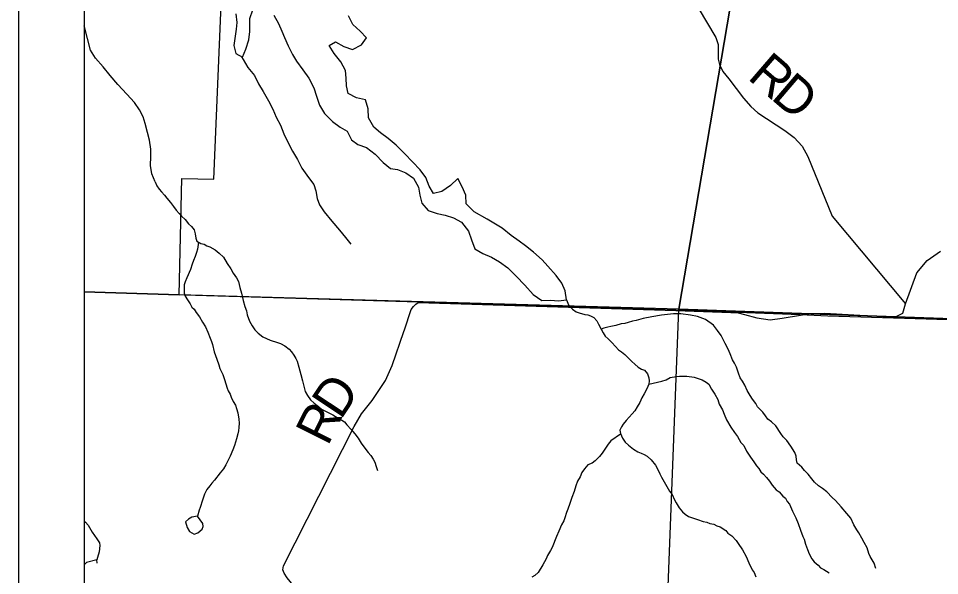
# Model space of a CAD drawing. Extents: x 0 to 34, y 0 to 22.
# Drawn here: x 2 to 3.401, y 19.379 to 20.228 of the extents above; entities that cross this region are included whole.
import ezdxf

# ---------------------------------------------------------------- set-up
doc = ezdxf.new("R2010")
doc.units = 0
for name, color, linetype in [('Default', 7, 'Continuous'), ('GM_X_County_Road', 7, 'Continuous'), ('GM_X_County_Road_Text', 7, 'Continuous'), ('GM_X_Major_Lake', 7, 'Continuous'), ('GM_X_Minor_River', 7, 'Continuous'), ('GM_X_Section', 7, 'Continuous'), ('GM_X_State_Route', 7, 'Continuous'), ('SH_Data', 7, 'Continuous')]:
    doc.layers.add(name, color=color, linetype=linetype)

msp = doc.modelspace()

# ---------------------------------------------------------------- linework, layer by layer
at = {"layer": 'Default'}
for points in [[(2.1, 20.7541), (2.1, 19.8111), (2.2447, 19.8069), (2.2486, 19.9841), (2.2971, 19.9829), (2.3292, 20.7433)], [(2.1, 19.8111), (2.1, 18.8179), (2.9671, 18.8096), (3.0048, 19.785), (2.2447, 19.8069)]]:
    msp.add_lwpolyline(points, close=True, dxfattribs=at)
at = {"layer": 'GM_X_County_Road'}
for points in [[(3.0342, 20.2435), (3.0612, 20.1987), (3.0648, 20.1877), (3.0644, 20.1657), (3.0666, 20.1575), (3.0719, 20.1469), (3.0808, 20.1355), (3.1031, 20.1064), (3.1141, 20.0933), (3.1251, 20.0837), (3.166, 20.057), (3.1802, 20.0464), (3.1923, 20.0333), (3.2008, 20.0173), (3.2382, 19.9266), (3.3496, 19.7928), (3.3669, 19.8402), (3.3827, 19.8589), (3.403, 19.8734)], [(2.5863, 19.7508), (2.5873, 19.7536), (2.5977, 19.7842), (2.6012, 19.7891), (2.6046, 19.7927), (2.6082, 19.795), (3.0004, 19.7831), (3.0837, 19.7798), (3.0891, 19.7798), (3.0949, 19.7794), (3.1045, 19.7767), (3.1233, 19.7717), (3.1436, 19.7685), (3.1618, 19.771), (3.1898, 19.7756), (3.2063, 19.7785), (3.2271, 19.779), (3.3334, 19.7729), (3.3456, 19.779), (3.3496, 19.7928)], [(2.4536, 18.3939), (2.4734, 18.9711), (2.4789, 19.2126), (2.4779, 19.2343), (2.4729, 19.258), (2.466, 19.2847), (2.4564, 19.3082), (2.4379, 19.3402), (2.4089, 19.3759), (2.4042, 19.3829), (2.4024, 19.3879), (2.4033, 19.3939), (2.5108, 19.6061), (2.522, 19.6255), (2.5381, 19.646), (2.5504, 19.6643), (2.5583, 19.6763), (2.5688, 19.6992), (2.5863, 19.7508)]]:
    msp.add_lwpolyline(points, dxfattribs=at)
at = {"layer": 'GM_X_Major_Lake'}
for points in [[(2.3308, 20.2347), (2.3324, 20.2213), (2.3311, 20.2115), (2.3275, 20.1864), (2.3306, 20.1742), (2.3407, 20.1687), (2.3459, 20.1807), (2.3504, 20.1951), (2.3522, 20.2079), (2.3521, 20.2174), (2.3523, 20.2273), (2.3564, 20.2405)], [(2.3885, 20.2326), (2.3958, 20.2199), (2.4009, 20.2084), (2.4048, 20.1988), (2.4102, 20.1857), (2.4171, 20.1726), (2.423, 20.1626), (2.4329, 20.1495), (2.4418, 20.1367), (2.4494, 20.1217), (2.4537, 20.1094), (2.4579, 20.0957), (2.4656, 20.0826), (2.4779, 20.0705), (2.4894, 20.0622), (2.5003, 20.0559), (2.5065, 20.0428), (2.5162, 20.0354), (2.5294, 20.0309), (2.5428, 20.0211), (2.5551, 20.0083), (2.5662, 19.9989), (2.5768, 19.9975), (2.5893, 19.9927), (2.6012, 19.9844), (2.6089, 19.9709), (2.6105, 19.9587), (2.6136, 19.9461), (2.6236, 19.9353), (2.6372, 19.9304), (2.6493, 19.9282), (2.6617, 19.9241), (2.6741, 19.9174), (2.6848, 19.9038), (2.6891, 19.8904), (2.6945, 19.877), (2.7068, 19.8695), (2.72, 19.8639), (2.732, 19.8568), (2.7447, 19.8477), (2.7573, 19.8353), (2.7707, 19.8213), (2.7833, 19.8073), (2.7964, 19.7983), (2.8093, 19.7984), (2.8218, 19.7977), (2.834, 19.7989), (2.832, 19.8127), (2.8266, 19.8246), (2.8181, 19.8362), (2.8055, 19.8502), (2.7966, 19.8599), (2.7836, 19.8719), (2.7717, 19.8813), (2.7616, 19.8884), (2.7496, 19.897), (2.7358, 19.908), (2.7231, 19.9159), (2.713, 19.9222), (2.6935, 19.9333), (2.6812, 19.9454), (2.6808, 19.9587), (2.675, 19.9714), (2.6684, 19.9841), (2.6575, 19.9733), (2.6444, 19.9641), (2.6314, 19.9609), (2.6249, 19.9721)], [(2.6249, 19.9721), (2.6198, 19.9852), (2.611, 19.9971), (2.588, 20.0212), (2.5746, 20.0345), (2.5627, 20.0446), (2.5508, 20.0536), (2.5407, 20.0618), (2.5327, 20.0761), (2.5322, 20.0902), (2.528, 20.1036), (2.5144, 20.1069), (2.5016, 20.1133), (2.4992, 20.1248), (2.4987, 20.1366), (2.4975, 20.1484), (2.4906, 20.1615), (2.4806, 20.1742), (2.4729, 20.1866), (2.4825, 20.1921), (2.4953, 20.1849), (2.5084, 20.1801), (2.5219, 20.1874), (2.5297, 20.1982), (2.5197, 20.2083), (2.5089, 20.2185), (2.5024, 20.2315)], [(2.1, 20.208), (2.102, 20.2086), (2.1, 20.2162)]]:
    msp.add_lwpolyline(points, dxfattribs=at)
at = {"layer": 'GM_X_Minor_River'}
for p, q in [((2.2808, 19.4587), (2.2722, 19.4695)), ((2.1199, 19.398), (2.1193, 19.4031))]:
    msp.add_line(p, q, dxfattribs=at)
for points in [[(2.2079, 19.9787), (2.203, 19.9911), (2.2007, 20.0037), (2.2017, 20.0174), (2.2016, 20.0284), (2.1996, 20.0422), (2.1965, 20.0537), (2.193, 20.0678), (2.1898, 20.0778), (2.184, 20.0885), (2.1766, 20.0997), (2.1648, 20.1125), (2.1514, 20.1269), (2.1396, 20.1405), (2.1289, 20.1537), (2.1174, 20.1669), (2.1097, 20.1792), (2.1003, 20.215)], [(2.3396, 20.1693), (2.342, 20.165), (2.3489, 20.153), (2.3592, 20.1409), (2.3653, 20.1282), (2.3726, 20.1162), (2.3806, 20.1023), (2.3871, 20.0896), (2.3921, 20.0773), (2.3986, 20.065), (2.4039, 20.0519), (2.4097, 20.0392), (2.4169, 20.0253), (2.4246, 20.0126), (2.4311, 19.9994), (2.4413, 19.9855)], [(2.4413, 19.9855), (2.4492, 19.9745), (2.4523, 19.9649), (2.4546, 19.9534), (2.4582, 19.9438), (2.4654, 19.9329), (2.4768, 19.9189), (2.4886, 19.9053), (2.4977, 19.894), (2.5058, 19.8839)], [(2.2079, 19.9787), (2.2104, 19.9729), (2.214, 19.9678), (2.2176, 19.9635), (2.2224, 19.9584), (2.226, 19.9537), (2.2315, 19.9471), (2.2358, 19.9412), (2.2402, 19.9357), (2.2446, 19.9306), (2.2482, 19.9263), (2.2537, 19.9212), (2.2588, 19.9149), (2.2632, 19.9106), (2.2676, 19.9055), (2.269, 19.8998), (2.2699, 19.8929), (2.2712, 19.8883), (2.2776, 19.885), (2.2828, 19.8837), (2.2869, 19.8813), (2.2914, 19.8796), (2.2992, 19.8752), (2.3055, 19.8704), (2.3118, 19.8641), (2.3175, 19.8544), (2.3233, 19.8462), (2.3269, 19.8396), (2.3319, 19.8326), (2.3348, 19.8268), (2.3371, 19.818), (2.3395, 19.8095), (2.3421, 19.798), (2.3445, 19.7888), (2.3469, 19.7823), (2.3482, 19.7765), (2.3517, 19.7665), (2.3556, 19.7596), (2.3599, 19.7533), (2.3647, 19.7486), (2.3721, 19.743), (2.3829, 19.7377), (2.3942, 19.7343), (2.3987, 19.7326), (2.4054, 19.7293), (2.4117, 19.7242), (2.4154, 19.7199), (2.419, 19.7148), (2.4222, 19.7098), (2.4243, 19.7055), (2.4267, 19.6967), (2.4297, 19.6856), (2.4321, 19.676), (2.4337, 19.6695), (2.4364, 19.6595), (2.4396, 19.6533), (2.4443, 19.647), (2.4499, 19.6419), (2.4565, 19.6367), (2.4613, 19.6328), (2.4703, 19.6279), (2.4781, 19.6238), (2.4863, 19.619), (2.4922, 19.6157), (2.4963, 19.6133), (2.4996, 19.6086), (2.5062, 19.6016), (2.512, 19.5949), (2.5171, 19.5883), (2.5214, 19.5809), (2.5272, 19.5731), (2.5323, 19.5668), (2.5363, 19.5621), (2.5399, 19.5563), (2.542, 19.5517), (2.5445, 19.5451), (2.5465, 19.539)], [(2.2738, 19.887), (2.2727, 19.8765), (2.271, 19.8712), (2.2689, 19.8652), (2.2664, 19.8592), (2.2643, 19.8532), (2.2618, 19.8453), (2.256, 19.8326), (2.2539, 19.8266), (2.2522, 19.8221), (2.252, 19.8171), (2.2522, 19.8095), (2.2539, 19.8045), (2.2571, 19.7991), (2.2611, 19.7929), (2.2636, 19.7878), (2.2676, 19.785), (2.2705, 19.78), (2.2756, 19.773), (2.2802, 19.7652), (2.2845, 19.7579), (2.2881, 19.7501), (2.2915, 19.7409), (2.2936, 19.7355), (2.2954, 19.7309), (2.298, 19.7201), (2.3018, 19.7086), (2.3049, 19.7001), (2.3066, 19.6944), (2.3109, 19.6855), (2.3133, 19.6778), (2.3174, 19.6647), (2.3191, 19.6605), (2.3224, 19.6554), (2.3237, 19.6508), (2.3269, 19.6443), (2.3302, 19.6385), (2.3319, 19.6338), (2.3336, 19.6273), (2.3351, 19.6174), (2.3357, 19.6113), (2.3354, 19.6045), (2.3349, 19.5999), (2.334, 19.595), (2.3318, 19.5875), (2.3288, 19.5773), (2.3263, 19.5706), (2.3222, 19.5612), (2.3189, 19.5552), (2.3156, 19.5481), (2.312, 19.5418), (2.3068, 19.5355), (2.2981, 19.5244), (2.2942, 19.52), (2.291, 19.5159), (2.2866, 19.5104), (2.2833, 19.5033), (2.2817, 19.4988), (2.28, 19.4943), (2.2766, 19.483), (2.2749, 19.4789), (2.2722, 19.4695)], [(2.834, 19.7989), (2.837, 19.7915), (2.8428, 19.7849), (2.8484, 19.7809), (2.8533, 19.7792), (2.8615, 19.777), (2.8664, 19.7761), (2.8706, 19.7748), (2.8754, 19.772), (2.8802, 19.7672), (2.8827, 19.7622), (2.8866, 19.7545), (2.8898, 19.7487), (2.8927, 19.744), (2.8971, 19.7397), (2.9026, 19.7342), (2.9084, 19.7279), (2.9132, 19.7232), (2.9173, 19.72), (2.9228, 19.716), (2.9272, 19.7113), (2.9335, 19.705), (2.9379, 19.7014), (2.943, 19.6967), (2.9479, 19.6934), (2.9524, 19.6922), (2.9571, 19.6867), (2.9592, 19.6805), (2.9598, 19.6759), (2.9592, 19.6706), (2.9563, 19.6635), (2.9519, 19.6561), (2.9486, 19.6501), (2.9453, 19.6426), (2.9413, 19.6363), (2.9377, 19.6299), (2.9337, 19.6255), (2.929, 19.6204), (2.9247, 19.6156), (2.9203, 19.6097), (2.9175, 19.6056), (2.915, 19.6007), (2.916, 19.5954), (2.9192, 19.5884), (2.9231, 19.5826), (2.9283, 19.5778), (2.9357, 19.5715), (2.9424, 19.5678), (2.9476, 19.5658), (2.9521, 19.5637), (2.9566, 19.5613), (2.9628, 19.5554), (2.9694, 19.5475), (2.9726, 19.541), (2.9761, 19.534), (2.9786, 19.5293), (2.9843, 19.5185), (2.9908, 19.508), (2.9948, 19.5029), (2.9983, 19.4945), (3.0008, 19.4898), (3.0051, 19.4824), (3.0102, 19.4762), (3.0146, 19.4726), (3.0195, 19.4694), (3.033, 19.4644), (3.0416, 19.4618), (3.0472, 19.4605), (3.0517, 19.4584), (3.0582, 19.4574), (3.0626, 19.455), (3.0679, 19.4533), (3.0761, 19.4481), (3.0793, 19.4438), (3.0856, 19.4397), (3.0922, 19.4327), (3.0951, 19.428), (3.1016, 19.4183), (3.1073, 19.4082), (3.1115, 19.3986), (3.1161, 19.3881), (3.1194, 19.3838), (3.1218, 19.3773)], [(3.3045, 19.39), (3.3017, 19.3981), (3.296, 19.4081), (3.2939, 19.4131), (3.2912, 19.4216), (3.2865, 19.4294), (3.2833, 19.4363), (3.2787, 19.4441), (3.2758, 19.4491), (3.2711, 19.4565), (3.2662, 19.4669), (3.2603, 19.474), (3.2519, 19.4841), (3.2432, 19.4936), (3.238, 19.4979), (3.23, 19.507), (3.2233, 19.5117), (3.2173, 19.5157), (3.2111, 19.5213), (3.2071, 19.5264), (3.2016, 19.5338), (3.1958, 19.5393), (3.1921, 19.5444), (3.1848, 19.5503), (3.1838, 19.5553), (3.1832, 19.561), (3.1811, 19.5668), (3.175, 19.5761), (3.1689, 19.5847), (3.1637, 19.5906), (3.1601, 19.5956), (3.1522, 19.6073), (3.1459, 19.6132), (3.14, 19.6176), (3.1364, 19.6227), (3.1324, 19.6281), (3.1247, 19.636), (3.1218, 19.6414), (3.1168, 19.6481), (3.1135, 19.6535), (3.1085, 19.6613), (3.105, 19.669), (3.1018, 19.6752), (3.0981, 19.6803), (3.0953, 19.6876), (3.0926, 19.6964), (3.0894, 19.7026), (3.0866, 19.708), (3.0831, 19.7169), (3.0799, 19.7238), (3.0753, 19.7327), (3.0724, 19.7385), (3.0692, 19.7447), (3.0634, 19.7525), (3.0573, 19.7607), (3.0454, 19.7691), (3.0334, 19.7737), (3.0225, 19.776), (3.0077, 19.7776), (2.9967, 19.778), (2.9784, 19.7756), (2.9635, 19.7731), (2.9505, 19.7709), (2.9398, 19.7675), (2.9344, 19.7665), (2.9279, 19.7644), (2.9226, 19.7631), (2.9168, 19.7625), (2.9088, 19.7602), (2.9015, 19.7585), (2.8965, 19.7576), (2.8908, 19.7562), (2.8865, 19.7546)], [(2.9593, 19.6709), (2.9791, 19.6753), (2.9856, 19.6773), (2.9915, 19.6809), (3.0014, 19.6825), (3.006, 19.6827), (3.017, 19.6827), (3.0279, 19.6812), (3.0358, 19.679), (3.0403, 19.6773), (3.0463, 19.6737), (3.0503, 19.6705), (3.0546, 19.6631), (3.0593, 19.6554), (3.064, 19.6476), (3.066, 19.6403), (3.071, 19.6314), (3.0738, 19.6249), (3.0773, 19.6164), (3.0838, 19.6051), (3.0896, 19.5973), (3.0939, 19.5911), (3.0993, 19.5818), (3.1037, 19.5775), (3.1079, 19.5686), (3.1137, 19.5596), (3.1188, 19.5522), (3.1231, 19.5464), (3.1264, 19.5421), (3.1296, 19.5374), (3.1337, 19.5335), (3.1381, 19.5284), (3.1428, 19.5229), (3.1468, 19.5171), (3.153, 19.51), (3.1574, 19.5068), (3.1629, 19.5002), (3.167, 19.497), (3.1695, 19.4923), (3.1731, 19.488), (3.1777, 19.4772), (3.183, 19.4672), (3.1865, 19.4587), (3.19, 19.4483), (3.1934, 19.439), (3.1956, 19.4348), (3.1976, 19.4271), (3.2007, 19.419), (3.2031, 19.4125), (3.2071, 19.4048), (3.2107, 19.4004), (3.2166, 19.3953), (3.2202, 19.391), (3.2255, 19.3885), (3.2333, 19.3833)], [(2.9162, 19.5948), (2.9012, 19.5845), (2.8972, 19.5793), (2.892, 19.5715), (2.888, 19.5659), (2.884, 19.5607), (2.8777, 19.5541), (2.8727, 19.5505), (2.8665, 19.5477), (2.861, 19.5418), (2.8574, 19.5362), (2.8545, 19.5298), (2.8505, 19.5228), (2.8479, 19.516), (2.8454, 19.5074), (2.842, 19.4983), (2.839, 19.4889), (2.8361, 19.4803), (2.834, 19.4751), (2.8315, 19.4672), (2.8298, 19.4627), (2.8265, 19.4563), (2.8224, 19.447), (2.8187, 19.4387), (2.8121, 19.4222), (2.8096, 19.4174), (2.8052, 19.4099), (2.8027, 19.4047), (2.7978, 19.3954), (2.7906, 19.3838), (2.7859, 19.3794), (2.7809, 19.3766)], [(2.2722, 19.4695), (2.2639, 19.4683), (2.2589, 19.4654), (2.2542, 19.461), (2.2566, 19.4525), (2.2603, 19.4464), (2.2674, 19.4424), (2.2732, 19.4445), (2.2794, 19.4497), (2.281, 19.4538), (2.2808, 19.4587)], [(2.1, 19.4621), (2.1019, 19.4605), (2.1059, 19.4562), (2.1124, 19.4453), (2.1192, 19.4352), (2.1236, 19.429), (2.1238, 19.4248), (2.1227, 19.4153), (2.1205, 19.4067), (2.1193, 19.4031)], [(2.1193, 19.4031), (2.1036, 19.3992), (2.1, 19.3958)]]:
    msp.add_lwpolyline(points, dxfattribs=at)
at = {"layer": 'GM_X_Section'}
for points in [[(2.3292, 20.7433), (3.1645, 20.7261), (3.0048, 19.785), (2.2447, 19.8069), (2.2486, 19.9841), (2.2971, 19.9829)], [(3.1645, 20.7261), (4.3261, 20.699), (4.3194, 20.2817), (4.3193, 20.2753), (4.3164, 20.0605), (4.2362, 19.9572), (4.2253, 19.9438), (4.2171, 19.9357), (4.2598, 19.9346), (4.2313, 19.8855), (4.2007, 19.856), (4.1813, 19.8371), (4.1568, 19.8116), (4.1378, 19.745), (3.0048, 19.785)]]:
    msp.add_lwpolyline(points, close=True, dxfattribs=at)
msp.add_lwpolyline([(3.9584, 18.8022), (2.9671, 18.8096), (3.0048, 19.785), (4.1378, 19.745)], dxfattribs=at)
at = {"layer": 'GM_X_State_Route'}
msp.add_lwpolyline([(3.4964, 19.7659), (3.3482, 19.7707), (3.2315, 19.7745), (3.1896, 19.7761), (3.0947, 19.7799), (3.0889, 19.7803), (3.0835, 19.7803), (3.0002, 19.7836), (2.608, 19.7955), (2.1, 19.8108), (2.1, 16.7408)], dxfattribs=at)
at = {"layer": 'SH_Data'}
for p, q in [((2, 21), (2, 14)), ((2.1, 20.9), (2.1, 14.1))]:
    msp.add_line(p, q, dxfattribs=at)

# ---------------------------------------------------------------- texts
at = {"layer": 'GM_X_County_Road_Text'}
for s, rotation, p in [('R', 319.2371, (3.1077, 20.1366)), ('D', 319.5239, (3.1433, 20.1059)), ('D', 56.3414, (2.4904, 19.6154)), ('R', 63.5178, (2.4705, 19.5752))]:
    msp.add_text(s, height=0.0568, rotation=rotation, dxfattribs=at).set_placement(p)

doc.saveas('drawing.dxf')
